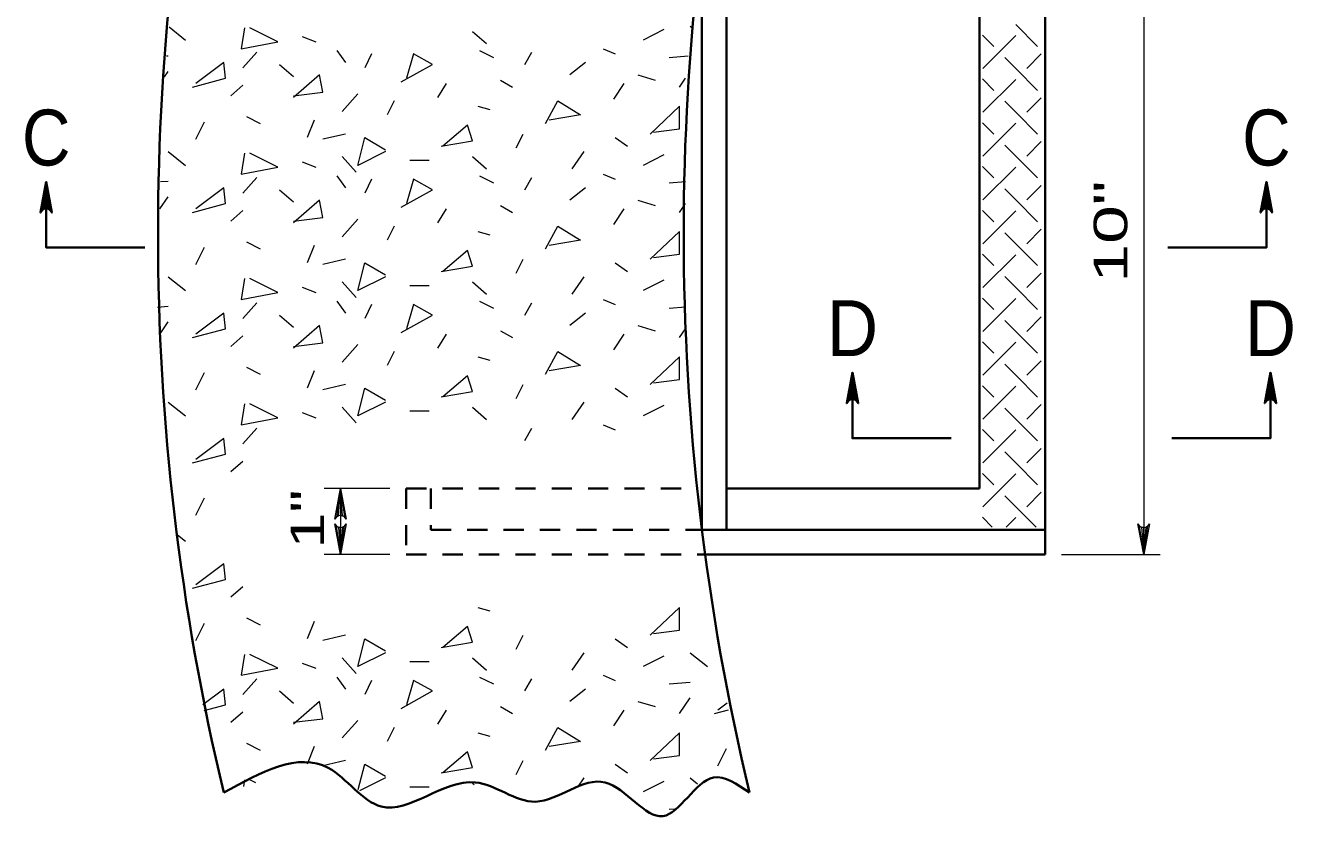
# Model space of a CAD drawing. Extents: x 16 to 133, y -56 to 112.
# Drawn here: x 62.74 to 101.31, y 71.48 to 95.61 of the extents above; entities that cross this region are included whole.
import ezdxf
from ezdxf.enums import TextEntityAlignment as Align

# ---------------------------------------------------------------- set-up
doc = ezdxf.new("R2010")
doc.units = 0
doc.header["$LTSCALE"] = 0.41
doc.linetypes.add('SHORT_DASHED', pattern=[2.7, 1.5, -1.2])
for name, color, linetype, lineweight in [('1', 7, 'Continuous', 35), ('10', 7, 'Continuous', 13), ('12', 7, 'Continuous', 53), ('13', 7, 'Continuous', 25), ('6', 7, 'Continuous', 13)]:
    doc.layers.add(name, color=color, linetype=linetype, lineweight=lineweight)

msp = doc.modelspace()

# ---------------------------------------------------------------- linework, layer by layer
at = {"layer": '1'}
for p, q in [((93.7728, 99.017), (93.7728, 79.517)), ((83.3277, 98.267), (83.3277, 80.267)), ((84.0777, 98.267), (84.0777, 80.267)), ((91.7728, 97.017), (91.7728, 81.517)), ((84.0777, 81.517), (91.7728, 81.517)), ((83.3277, 80.267), (93.7728, 80.267)), ((83.4245, 79.517), (93.7728, 79.517))]:
    msp.add_line(p, q, dxfattribs=at)
at = {"layer": '1', "linetype": 'SHORT_DASHED'}
for p, q in [((74.3277, 81.517), (74.3277, 79.517)), ((74.3277, 81.517), (83.1839, 81.517)), ((75.0777, 81.517), (75.0777, 80.267)), ((75.0777, 80.267), (83.3277, 80.267)), ((74.3277, 79.517), (83.4245, 79.517))]:
    msp.add_line(p, q, dxfattribs=at)
at = {"layer": '1'}
for centre in [(140.0228, 89.267), (156.0228, 89.267)]:
    msp.add_arc(centre, 73.25, 166.58032, 193.41967, dxfattribs=at)
msp.add_spline([(68.7728, 72.267), (71.9559, 73.0185), (73.5682, 71.8453), (76.4262, 72.5785), (78.2583, 71.9919), (80.3834, 72.5785), (82.1422, 71.552), (83.6811, 72.7252), (84.7728, 72.267)], degree=3, dxfattribs=at)
at = {"layer": '10'}
for p, q in [((96.7728, 99.017), (96.7728, 79.517)), ((73.8277, 81.517), (71.8277, 81.517)), ((72.3277, 81.517), (72.3277, 79.517)), ((73.8277, 79.517), (71.8277, 79.517)), ((94.2728, 79.517), (97.2728, 79.517))]:
    msp.add_line(p, q, dxfattribs=at)
at = {"layer": '10', "lineweight": 35}
for points in [[(63.37, 90.8479), (63.1952, 89.9158), (63.245, 89.9877), (63.3075, 90.0247), (63.37, 90.0354), (63.4325, 90.0247), (63.495, 89.9877), (63.5448, 89.9158), (63.37, 90.8479), (63.495, 89.9877), (63.4325, 90.0247), (63.37, 90.8479), (63.37, 90.0354), (63.3075, 90.0247), (63.37, 90.8479), (63.245, 89.9877)], [(66.37, 88.8479), (63.37, 88.8479), (63.37, 90.8479)], [(97.5071, 88.8479), (100.5071, 88.8479), (100.5071, 90.8479)], [(100.5071, 90.8479), (100.6818, 89.9158), (100.6321, 89.9877), (100.5696, 90.0247), (100.5071, 90.0354), (100.4446, 90.0247), (100.3821, 89.9877), (100.3323, 89.9158), (100.5071, 90.8479), (100.3821, 89.9877), (100.4446, 90.0247), (100.5071, 90.8479), (100.5071, 90.0354), (100.5696, 90.0247), (100.5071, 90.8479), (100.6321, 89.9877)], [(87.9102, 85.0487), (87.7355, 84.1167), (87.7852, 84.1885), (87.8477, 84.2255), (87.9102, 84.2362), (87.9727, 84.2255), (88.0352, 84.1885), (88.085, 84.1167), (87.9102, 85.0487), (88.0352, 84.1885), (87.9727, 84.2255), (87.9102, 85.0487), (87.9102, 84.2362), (87.8477, 84.2255), (87.9102, 85.0487), (87.7852, 84.1885)], [(90.9102, 83.0487), (87.9102, 83.0487), (87.9102, 85.0487)], [(97.6304, 83.0487), (100.6304, 83.0487), (100.6304, 85.0487)], [(100.6304, 85.0487), (100.8051, 84.1167), (100.7554, 84.1885), (100.6929, 84.2255), (100.6304, 84.2362), (100.5679, 84.2255), (100.5054, 84.1885), (100.4556, 84.1167), (100.6304, 85.0487), (100.5054, 84.1885), (100.5679, 84.2255), (100.6304, 85.0487), (100.6304, 84.2362), (100.6929, 84.2255), (100.6304, 85.0487), (100.7554, 84.1885)]]:
    msp.add_lwpolyline(points, dxfattribs=at)
at = {"layer": '10'}
for points in [[(72.3277, 81.517), (72.5025, 80.5849), (72.4527, 80.6567), (72.3902, 80.6937), (72.3277, 80.7045), (72.2652, 80.6937), (72.2027, 80.6567), (72.153, 80.5849), (72.3277, 81.517), (72.2027, 80.6567), (72.2652, 80.6937), (72.3277, 81.517), (72.3277, 80.7045), (72.3902, 80.6937), (72.3277, 81.517), (72.4527, 80.6567)], [(72.3277, 79.517), (72.153, 80.449), (72.2027, 80.3772), (72.2652, 80.3402), (72.3277, 80.3295), (72.3902, 80.3402), (72.4527, 80.3772), (72.5025, 80.449), (72.3277, 79.517), (72.4527, 80.3772), (72.3902, 80.3402), (72.3277, 79.517), (72.3277, 80.3295), (72.2652, 80.3402), (72.3277, 79.517), (72.2027, 80.3772)], [(96.7728, 79.517), (96.598, 80.449), (96.6478, 80.3772), (96.7103, 80.3402), (96.7728, 80.3295), (96.8353, 80.3402), (96.8978, 80.3772), (96.9475, 80.449), (96.7728, 79.517), (96.8978, 80.3772), (96.8353, 80.3402), (96.7728, 79.517), (96.7728, 80.3295), (96.7103, 80.3402), (96.7728, 79.517), (96.6478, 80.3772)]]:
    msp.add_lwpolyline(points, dxfattribs=at)
at = {"layer": '6'}
for p, q in [((67.1127, 95.5627), (67.6099, 95.1649)), ((76.3469, 95.4296), (76.7705, 95.059)), ((82.1715, 95.4826), (81.5361, 95.1649)), ((82.9658, 95.5885), (83.0102, 95.553)), ((91.8655, 95.3142), (92.2118, 94.9679)), ((91.8784, 94.3013), (92.8784, 95.3013)), ((93.5451, 94.9679), (92.8784, 95.6346)), ((71.1576, 95.2708), (71.5812, 95.1119)), ((80.3182, 94.9001), (80.6889, 94.7412)), ((67.0307, 94.6842), (67.0804, 94.6883)), ((69.3573, 94.3176), (69.7809, 94.7942)), ((72.2167, 94.8472), (72.4814, 94.4765)), ((73.2757, 94.7412), (73.0639, 94.3176)), ((76.5587, 94.8472), (76.9823, 94.6354)), ((77.9354, 94.4235), (78.1472, 94.7942)), ((82.3304, 94.6354), (82.907, 94.6834)), ((92.5451, 94.6346), (92.8784, 94.3013)), ((93.653, 94.7426), (93.2118, 94.3013)), ((66.9714, 94.0483), (67.0804, 94.2117)), ((70.4693, 94.4235), (70.8929, 94.0529)), ((79.7887, 94.4765), (79.3121, 94.1058)), ((93.5451, 93.6346), (92.8784, 94.3013)), ((68.9866, 93.4704), (69.3573, 93.7881)), ((75.2878, 93.4175), (75.5526, 93.8411)), ((77.1941, 93.947), (77.5648, 93.7352)), ((80.9536, 93.8411), (80.6359, 93.3645)), ((81.3773, 94.1058), (81.9068, 93.947)), ((82.6481, 93.7352), (82.8262, 94.0024)), ((91.8655, 93.9809), (92.2118, 93.6346)), ((91.8784, 92.9679), (92.8784, 93.9679)), ((72.8521, 93.5234), (72.3755, 92.9939)), ((93.2118, 92.9679), (93.653, 93.4092)), ((73.9641, 93.3116), (73.7523, 92.888)), ((76.5057, 93.1527), (76.8764, 93.0468)), ((92.5451, 93.3013), (92.8784, 92.9679)), ((93.5451, 92.3013), (92.8784, 92.9679)), ((67.9276, 92.1466), (68.1924, 92.6761)), ((69.4632, 92.835), (69.8868, 92.6232)), ((71.5283, 92.7291), (71.3165, 92.1996)), ((91.8655, 92.6476), (92.2118, 92.3013)), ((91.8784, 91.6346), (92.8784, 92.6346)), ((72.4814, 92.3055), (71.7931, 92.1466)), ((77.6707, 91.8819), (77.8825, 92.3055)), ((80.6889, 92.1996), (81.0595, 91.9348)), ((92.5451, 91.9679), (92.8784, 91.6346)), ((93.653, 92.0759), (93.2118, 91.6346)), ((67.0804, 91.776), (67.6099, 91.3524)), ((71.1576, 91.4583), (71.5812, 91.2994)), ((72.3755, 91.6171), (72.7991, 91.1406)), ((74.4406, 91.5112), (75.0231, 91.5112)), ((76.3469, 91.6171), (76.7705, 91.2465)), ((79.7358, 91.776), (79.3651, 91.2465)), ((82.1715, 91.6701), (81.5361, 91.3524)), ((93.5451, 90.9679), (92.8784, 91.6346)), ((72.2167, 91.0347), (72.4814, 90.664)), ((76.5587, 91.0347), (76.9823, 90.8229)), ((80.3182, 91.0876), (80.6889, 90.9287)), ((91.8655, 91.3142), (92.2118, 90.9679)), ((91.8784, 90.3013), (92.8784, 91.3013)), ((66.8481, 90.8564), (67.0804, 90.8758)), ((69.3573, 90.5051), (69.7809, 90.9817)), ((73.2757, 90.9287), (73.0639, 90.5051)), ((77.9354, 90.611), (78.1472, 90.9817)), ((79.7887, 90.664), (79.3121, 90.2933)), ((82.3304, 90.8229), (82.8257, 90.8641)), ((93.2118, 90.3013), (93.653, 90.7426)), ((66.8315, 90.0259), (67.0804, 90.3992)), ((70.4693, 90.611), (70.8929, 90.2404)), ((81.3773, 90.2933), (81.9068, 90.1345)), ((92.5451, 90.6346), (92.8784, 90.3013)), ((93.5451, 89.6346), (92.8784, 90.3013)), ((68.9866, 89.6579), (69.3573, 89.9756)), ((75.2878, 89.605), (75.5526, 90.0286)), ((77.1941, 90.1345), (77.5648, 89.9227)), ((80.9536, 90.0286), (80.6359, 89.552)), ((82.6481, 89.9227), (82.8257, 90.1891)), ((91.8655, 89.9809), (92.2118, 89.6346)), ((91.8784, 88.9679), (92.8784, 89.9679)), ((72.8521, 89.7109), (72.3755, 89.1814)), ((73.9641, 89.4991), (73.7523, 89.0755)), ((76.5057, 89.3402), (76.8764, 89.2343)), ((92.5451, 89.3013), (92.8784, 88.9679)), ((93.653, 89.4092), (93.2118, 88.9679)), ((67.9276, 88.3341), (68.1924, 88.8636)), ((69.4632, 89.0225), (69.8868, 88.8107)), ((71.5283, 88.9166), (71.3165, 88.3871)), ((93.5451, 88.3013), (92.8784, 88.9679)), ((72.4814, 88.493), (71.7931, 88.3341)), ((77.6707, 88.0694), (77.8825, 88.493)), ((80.6889, 88.3871), (81.0595, 88.1223)), ((91.8655, 88.6476), (92.2118, 88.3013)), ((91.8784, 87.6346), (92.8784, 88.6346)), ((67.0804, 87.9635), (67.6099, 87.5399)), ((79.7358, 87.9635), (79.3651, 87.434)), ((92.5451, 87.9679), (92.8784, 87.6346)), ((93.2118, 87.6346), (93.653, 88.0759)), ((71.1576, 87.6458), (71.5812, 87.4869)), ((72.3755, 87.8046), (72.7991, 87.3281)), ((74.4406, 87.6987), (75.0231, 87.6987)), ((76.3469, 87.8046), (76.7705, 87.434)), ((82.1715, 87.8576), (81.5361, 87.5399)), ((93.5451, 86.9679), (92.8784, 87.6346)), ((72.2167, 87.2222), (72.4814, 86.8515)), ((76.5587, 87.2222), (76.9823, 87.0104)), ((80.3182, 87.2751), (80.6889, 87.1162)), ((91.8655, 87.3142), (92.2118, 86.9679)), ((91.8784, 86.3013), (92.8784, 87.3013)), ((66.7613, 87.0367), (67.0804, 87.0633)), ((69.3573, 86.6926), (69.7809, 87.1692)), ((70.4693, 86.7985), (70.8929, 86.4279)), ((73.2757, 87.1162), (73.0639, 86.6926)), ((77.9354, 86.7985), (78.1472, 87.1692)), ((79.7887, 86.8515), (79.3121, 86.4808)), ((82.3304, 87.0104), (82.8257, 87.0516)), ((66.8166, 86.191), (67.0804, 86.5867)), ((81.3773, 86.4808), (81.9068, 86.322)), ((92.5451, 86.6346), (92.8784, 86.3013)), ((93.653, 86.7426), (93.2118, 86.3013)), ((68.9866, 85.8454), (69.3573, 86.1631)), ((75.2878, 85.7925), (75.5526, 86.2161)), ((77.1941, 86.322), (77.5648, 86.1102)), ((80.9536, 86.2161), (80.6359, 85.7395)), ((82.6481, 86.1102), (82.8257, 86.3766)), ((93.5451, 85.6346), (92.8784, 86.3013)), ((72.8521, 85.8984), (72.3755, 85.3689)), ((73.9641, 85.6866), (73.7523, 85.263)), ((91.8655, 85.9809), (92.2118, 85.6346)), ((91.8784, 84.9679), (92.8784, 85.9679)), ((76.5057, 85.5277), (76.8764, 85.4218)), ((92.5451, 85.3013), (92.8784, 84.9679)), ((93.2118, 84.9679), (93.653, 85.4092)), ((67.9276, 84.5216), (68.1924, 85.0511)), ((69.4632, 85.21), (69.8868, 84.9982)), ((71.5283, 85.1041), (71.3165, 84.5746)), ((93.5451, 84.3013), (92.8784, 84.9679)), ((72.4814, 84.6805), (71.7931, 84.5216)), ((77.6707, 84.2569), (77.8825, 84.6805)), ((80.6889, 84.5746), (81.0595, 84.3098)), ((91.8655, 84.6476), (92.2118, 84.3013)), ((91.8784, 83.6346), (92.8784, 84.6346)), ((67.0804, 84.151), (67.6099, 83.7274)), ((79.7358, 84.151), (79.3651, 83.6215)), ((71.1576, 83.8333), (71.5812, 83.6744)), ((72.3755, 83.9921), (72.7991, 83.5156)), ((74.4406, 83.8862), (75.0231, 83.8862)), ((76.3469, 83.9921), (76.7705, 83.6215)), ((82.1715, 84.0451), (81.5361, 83.7274)), ((92.5451, 83.9679), (92.8784, 83.6346)), ((93.653, 84.0759), (93.2118, 83.6346)), ((69.3573, 82.8801), (69.7809, 83.3567)), ((77.9354, 82.986), (78.1472, 83.3567)), ((80.3182, 83.4626), (80.6889, 83.3037)), ((93.5451, 82.9679), (92.8784, 83.6346)), ((67.0778, 83.2506), (67.0804, 83.2508)), ((91.8655, 83.3142), (92.2118, 82.9679)), ((91.8784, 82.3013), (92.8784, 83.3013)), ((92.5451, 82.6346), (92.8784, 82.3013)), ((93.2118, 82.3013), (93.653, 82.7426)), ((68.9866, 82.0329), (69.3573, 82.3506)), ((93.5451, 81.6346), (92.8784, 82.3013)), ((91.8655, 81.9809), (92.2118, 81.6346)), ((91.8784, 80.9679), (92.8784, 81.9679)), ((93.653, 81.4092), (93.2118, 80.9679)), ((67.9276, 80.7091), (68.1924, 81.2386)), ((92.5451, 81.3013), (92.8784, 80.9679)), ((91.8655, 80.6476), (92.1656, 80.3475)), ((92.5913, 80.3475), (92.8784, 80.6346)), ((93.4989, 80.3475), (92.8784, 80.9679)), ((67.3651, 80.1107), (67.6099, 79.9149)), ((68.9866, 78.2204), (69.3573, 78.5381)), ((69.4632, 77.585), (69.8868, 77.3732)), ((76.5057, 77.9027), (76.8764, 77.7968)), ((67.9276, 76.8966), (68.1924, 77.4261)), ((71.5283, 77.4791), (71.3165, 76.9496)), ((72.4814, 77.0555), (71.7931, 76.8966)), ((77.6707, 76.6319), (77.8825, 77.0555)), ((80.6889, 76.9496), (81.0595, 76.6848)), ((79.7358, 76.526), (79.3651, 75.9965)), ((82.1715, 76.4201), (81.5361, 76.1024)), ((82.9658, 76.526), (83.4953, 76.1024)), ((71.1576, 76.2083), (71.5812, 76.0494)), ((72.3755, 76.3671), (72.7991, 75.8906)), ((74.4406, 76.2612), (75.0231, 76.2612)), ((76.3469, 76.3671), (76.7705, 75.9965)), ((69.3573, 75.2551), (69.7809, 75.7317)), ((72.2167, 75.7847), (72.4814, 75.414)), ((73.2757, 75.6787), (73.0639, 75.2551)), ((76.5587, 75.7847), (76.9823, 75.5729)), ((77.9354, 75.361), (78.1472, 75.7317)), ((80.3182, 75.8376), (80.6889, 75.6787)), ((82.3304, 75.5729), (82.9658, 75.6258)), ((70.4693, 75.361), (70.8929, 74.9904)), ((79.7887, 75.414), (79.3121, 75.0433)), ((77.1941, 74.8845), (77.5648, 74.6727)), ((81.3773, 75.0433), (81.9068, 74.8845)), ((82.6481, 74.6727), (82.9658, 75.1492)), ((84.0949, 74.99), (83.813, 74.7786)), ((68.9866, 74.4079), (69.3573, 74.7256)), ((72.8521, 74.4609), (72.3755, 73.9314)), ((75.2878, 74.355), (75.5526, 74.7786)), ((80.9536, 74.7786), (80.6359, 74.302)), ((83.7071, 74.6727), (84.1348, 74.7852)), ((73.9641, 74.2491), (73.7523, 73.8255)), ((76.5057, 74.0902), (76.8764, 73.9843)), ((69.4632, 73.7725), (69.8868, 73.5607)), ((71.5283, 73.6666), (71.3165, 73.1371)), ((83.813, 73.0841), (84.0778, 73.6136)), ((72.4814, 73.243), (71.7931, 73.0841)), ((77.6707, 72.8194), (77.8825, 73.243)), ((80.6889, 73.1371), (81.0595, 72.8723)), ((69.4102, 72.6605), (69.3756, 72.4525)), ((69.7529, 72.5686), (69.5691, 72.6605)), ((73.6993, 72.7135), (72.9099, 72.3188)), ((76.3469, 72.5546), (76.3953, 72.5122)), ((79.7358, 72.7135), (79.5418, 72.4364)), ((82.1715, 72.6076), (81.5361, 72.2899)), ((82.9658, 72.7135), (83.1905, 72.5337)), ((74.4406, 72.4487), (75.0231, 72.4487)), ((82.3304, 71.7604), (82.4985, 71.7744))]:
    msp.add_line(p, q, dxfattribs=at)
for points in [[(69.4102, 95.5355), (69.3043, 94.9001), (70.4163, 95.1119), (69.5691, 95.5355)], [(74.1759, 93.894), (75.129, 94.4235), (74.5465, 94.7412), (74.3347, 93.9999)], [(67.8217, 93.7352), (68.8278, 93.9999), (68.7748, 94.4765), (67.9276, 93.8411)], [(70.8929, 93.4704), (71.7931, 93.5763), (71.6872, 94.1058), (70.8929, 93.4175)], [(78.5708, 92.6232), (78.9415, 93.3116), (79.6299, 92.888), (78.6767, 92.7291)], [(81.8538, 92.3584), (82.6481, 92.4644), (82.6481, 93.1527), (81.7479, 92.3055)], [(73.6993, 91.776), (72.8521, 91.3524), (73.0639, 92.1996), (73.6993, 91.8289)], [(75.3937, 91.9348), (76.3469, 92.0937), (76.188, 92.5703), (75.4467, 91.9348)], [(69.4102, 91.723), (69.3043, 91.0876), (70.4163, 91.2994), (69.5691, 91.723)], [(67.8217, 89.9227), (68.8278, 90.1874), (68.7748, 90.664), (67.9276, 90.0286)], [(74.1759, 90.0815), (75.129, 90.611), (74.5465, 90.9287), (74.3347, 90.1874)], [(70.8929, 89.6579), (71.7931, 89.7638), (71.6872, 90.2933), (70.8929, 89.605)], [(78.5708, 88.8107), (78.9415, 89.4991), (79.6299, 89.0755), (78.6767, 88.9166)], [(81.8538, 88.5459), (82.6481, 88.6519), (82.6481, 89.3402), (81.7479, 88.493)], [(75.3937, 88.1223), (76.3469, 88.2812), (76.188, 88.7578), (75.4467, 88.1223)], [(73.6993, 87.9635), (72.8521, 87.5399), (73.0639, 88.3871), (73.6993, 88.0164)], [(69.4102, 87.9105), (69.3043, 87.2751), (70.4163, 87.4869), (69.5691, 87.9105)], [(67.8217, 86.1102), (68.8278, 86.3749), (68.7748, 86.8515), (67.9276, 86.2161)], [(74.1759, 86.269), (75.129, 86.7985), (74.5465, 87.1162), (74.3347, 86.3749)], [(70.8929, 85.8454), (71.7931, 85.9513), (71.6872, 86.4808), (70.8929, 85.7925)], [(78.5708, 84.9982), (78.9415, 85.6866), (79.6299, 85.263), (78.6767, 85.1041)], [(81.8538, 84.7334), (82.6481, 84.8394), (82.6481, 85.5277), (81.7479, 84.6805)], [(75.3937, 84.3098), (76.3469, 84.4687), (76.188, 84.9453), (75.4467, 84.3098)], [(73.6993, 84.151), (72.8521, 83.7274), (73.0639, 84.5746), (73.6993, 84.2039)], [(69.4102, 84.098), (69.3043, 83.4626), (70.4163, 83.6744), (69.5691, 84.098)], [(67.8217, 82.2977), (68.8278, 82.5624), (68.7748, 83.039), (67.9276, 82.4036)], [(67.8217, 78.4852), (68.8278, 78.7499), (68.7748, 79.2265), (67.9276, 78.5911)], [(81.8538, 77.1084), (82.6481, 77.2144), (82.6481, 77.9027), (81.7479, 77.0555)], [(75.3937, 76.6848), (76.3469, 76.8437), (76.188, 77.3203), (75.4467, 76.6848)], [(73.6993, 76.526), (72.8521, 76.1024), (73.0639, 76.9496), (73.6993, 76.5789)], [(69.4102, 76.473), (69.3043, 75.8376), (70.4163, 76.0494), (69.5691, 76.473)], [(74.1759, 74.8315), (75.129, 75.361), (74.5465, 75.6787), (74.3347, 74.9374)], [(68.1793, 74.7668), (68.8278, 74.9374), (68.7748, 75.414), (68.1389, 74.9371)], [(70.8929, 74.4079), (71.7931, 74.5138), (71.6872, 75.0433), (70.8929, 74.355)], [(78.5708, 73.5607), (78.9415, 74.2491), (79.6299, 73.8255), (78.6767, 73.6666)], [(81.8538, 73.2959), (82.6481, 73.4019), (82.6481, 74.0902), (81.7479, 73.243)], [(75.3937, 72.8723), (76.3469, 73.0312), (76.188, 73.5078), (75.4467, 72.8723)], [(72.8694, 72.3593), (73.0639, 73.1371), (73.6993, 72.7664)]]:
    msp.add_lwpolyline(points, dxfattribs=at)

# ---------------------------------------------------------------- texts
at = {"layer": '12'}
for s, width, p in [('C', 0.9, (63.37, 91.3479)), ('C', 0.9, (100.5071, 91.3479)), ('D', 0.95, (87.9102, 85.5487)), ('D', 0.95, (100.6304, 85.5487))]:
    msp.add_text(s, height=1.7, dxfattribs=dict(at, width=width)).set_placement(p, align=Align.CENTER)
at = {"layer": '13'}
for s, width, p in [('10"', 1.55, (96.2728, 89.3386)), ('1"', 1.45, (71.8277, 80.5886))]:
    msp.add_text(s, height=1.02, rotation=90, dxfattribs=dict(at, width=width)).set_placement(p, align=Align.CENTER)

doc.saveas('drawing.dxf')
